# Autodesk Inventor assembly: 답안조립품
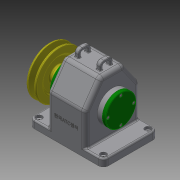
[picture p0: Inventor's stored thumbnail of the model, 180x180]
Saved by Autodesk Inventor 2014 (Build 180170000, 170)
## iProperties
Created: 2016-12
Part Number: 답안조립품
Document SubType Name: Assembly
Designer: NET
Author: NET
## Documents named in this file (15)
- C:\Users\NET\Desktop\461207V1018\답안조립품.iam
- C:\Users\NET\Desktop\461207V1018\본체.ipt
- C:\Users\NET\Desktop\461207V1018\V-벨트풀리.ipt
- C:\Users\NET\Desktop\461207V1018\뒤커버.ipt
- C:\Users\NET\Desktop\461207V1018\멈춤나사 - M4x10.ipt
- C:\Users\NET\Desktop\461207V1018\베어링 6203.ipt
- C:\Users\NET\Desktop\461207V1018\볼트 M3 x 8.ipt
- C:\Users\NET\Desktop\461207V1018\볼트 M3 x 10.ipt
- C:\Users\NET\Desktop\461207V1018\부시.ipt
- C:\Users\NET\Desktop\461207V1018\스퍼기어.ipt
- C:\Users\NET\Desktop\461207V1018\앞커버.ipt
- C:\Users\NET\Desktop\461207V1018\오일씰 28 40 8.ipt
- C:\Users\NET\Desktop\461207V1018\축.ipt
- C:\Users\NET\Desktop\461207V1018\키 - 5 x 5 x 18.ipt
- C:\Users\NET\Desktop\461207V1018\키 - 6 x 6 x 22.ipt
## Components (9 placed, 3 different names)
1. V-벨트풀리:1
2. ISO 4762 M3 x 8:1
3. ISO 4762 M3 x 8:2
4. ISO 4762 M3 x 8:3
5. ISO 4762 M3 x 8:4
6. ISO 4762 M3 x 10:1
7. ISO 4762 M3 x 10:2
8. ISO 4762 M3 x 10:3
9. ISO 4762 M3 x 10:4
